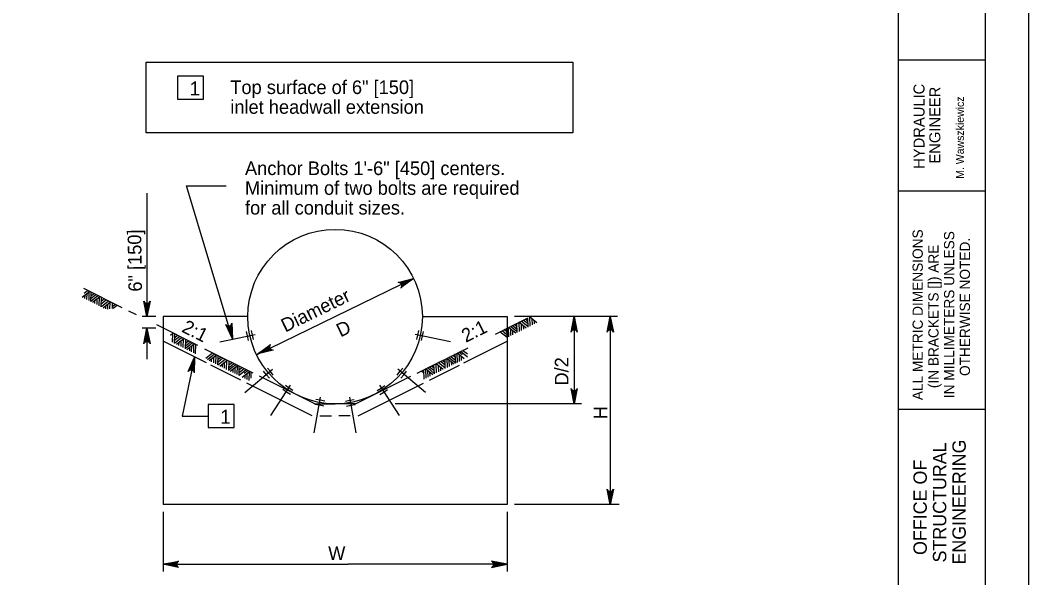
# Model space of a CAD drawing. Extents: x 1083.1 to 1117.1, y 675.4 to 741.4.
# Drawn here: x 1105.58 to 1117.13, y 728.43 to 734.81 of the extents above; entities that cross this region are included whole.
import ezdxf

# ---------------------------------------------------------------- set-up
doc = ezdxf.new("R2010")
doc.units = 0
doc.layers.add('Level 1', color=7, linetype='Continuous')

msp = doc.modelspace()

# ---------------------------------------------------------------- linework, layer by layer
at = {"layer": 'Level 1'}
for p, q in [((1115.636, 719.854), (1115.636, 740.854)), ((1116.626, 734.354), (1115.636, 734.354)), ((1107.384, 734.171), (1107.384, 733.909)), ((1107.683, 734.171), (1107.384, 734.171)), ((1107.683, 733.909), (1107.683, 734.171)), ((1107.384, 733.909), (1107.683, 733.909)), ((1108.013, 731.162), (1107.486, 732.915)), ((1107.486, 732.915), (1107.941, 732.915)), ((1107.034, 732.833), (1107.034, 731.418)), ((1116.626, 732.854), (1115.636, 732.854)), ((1110.085, 731.855), (1108.29, 730.98)), ((1109.928, 731.806), (1110.085, 731.855)), ((1109.938, 731.8), (1110.085, 731.855)), ((1109.947, 731.788), (1110.085, 731.855)), ((1109.95, 731.777), (1110.085, 731.855)), ((1109.95, 731.765), (1110.085, 731.855)), ((1106.751, 731.519), (1106.31, 731.74)), ((1106.293, 731.64), (1106.376, 731.707)), ((1106.316, 731.687), (1106.355, 731.718)), ((1106.324, 731.625), (1106.326, 731.667)), ((1106.347, 731.613), (1106.35, 731.685)), ((1106.371, 731.601), (1106.374, 731.705)), ((1106.392, 731.591), (1106.396, 731.697)), ((1106.392, 731.594), (1106.473, 731.658)), ((1106.393, 731.625), (1106.45, 731.67)), ((1106.394, 731.657), (1106.426, 731.682)), ((1106.411, 731.582), (1106.495, 731.648)), ((1106.463, 731.555), (1106.465, 731.625)), ((1106.487, 731.543), (1106.49, 731.644)), ((1106.511, 731.531), (1106.515, 731.638)), ((1106.514, 731.598), (1106.544, 731.623)), ((1106.438, 731.568), (1106.439, 731.604)), ((1106.512, 731.534), (1106.592, 731.599)), ((1106.513, 731.567), (1106.567, 731.611)), ((1106.534, 731.52), (1106.618, 731.586)), ((1106.562, 731.506), (1106.563, 731.543)), ((1106.586, 731.503), (1106.588, 731.563)), ((1106.611, 731.507), (1106.614, 731.583)), ((1106.638, 731.511), (1106.64, 731.575)), ((1106.638, 731.504), (1106.639, 731.505)), ((1106.639, 731.534), (1106.67, 731.56)), ((1106.649, 731.513), (1106.694, 731.548)), ((1107.011, 731.578), (1107.034, 731.418)), ((1107.022, 731.572), (1107.034, 731.418)), ((1107.058, 731.58), (1107.034, 731.418)), ((1107.048, 731.574), (1107.034, 731.418)), ((1107.034, 731.571), (1107.034, 731.418)), ((1106.916, 731.437), (1106.828, 731.481)), ((1107.136, 731.418), (1106.979, 731.418)), ((1107.219, 731.418), (1107.219, 729.265)), ((1108.189, 731.418), (1107.219, 731.418)), ((1110.186, 731.418), (1111.156, 731.418)), ((1111.021, 731.218), (1111.389, 731.402)), ((1111.156, 731.418), (1111.156, 729.265)), ((1112.419, 731.418), (1111.239, 731.418)), ((1111.394, 731.365), (1111.363, 731.389)), ((1111.396, 731.298), (1111.393, 731.404)), ((1111.497, 731.348), (1111.413, 731.414)), ((1111.42, 731.31), (1111.417, 731.411)), ((1111.445, 731.322), (1111.443, 731.391)), ((1111.898, 731.255), (1111.923, 731.418)), ((1111.909, 731.262), (1111.923, 731.418)), ((1111.923, 731.418), (1111.923, 730.732)), ((1111.923, 731.264), (1111.923, 731.418)), ((1111.934, 731.263), (1111.923, 731.418)), ((1111.945, 731.257), (1111.923, 731.418)), ((1112.312, 731.255), (1112.336, 731.418)), ((1112.322, 731.262), (1112.336, 731.418)), ((1112.336, 731.418), (1112.336, 730.217)), ((1112.336, 731.264), (1112.336, 731.418)), ((1112.348, 731.263), (1112.336, 731.418)), ((1112.359, 731.257), (1112.336, 731.418)), ((1107.136, 731.285), (1106.979, 731.285)), ((1107.009, 731.123), (1107.034, 731.285)), ((1107.019, 731.129), (1107.034, 731.285)), ((1107.034, 731.285), (1107.034, 730.931)), ((1107.034, 731.132), (1107.034, 731.285)), ((1107.045, 731.131), (1107.034, 731.285)), ((1107.056, 731.125), (1107.034, 731.285)), ((1107.616, 731.087), (1107.146, 731.322)), ((1107.955, 731.313), (1108.013, 731.162)), ((1107.967, 731.31), (1108.013, 731.162)), ((1107.978, 731.311), (1108.013, 731.162)), ((1107.991, 731.317), (1108.013, 731.162)), ((1108, 731.326), (1108.013, 731.162)), ((1111.155, 731.177), (1111.152, 731.284)), ((1111.255, 731.227), (1111.171, 731.293)), ((1111.177, 731.188), (1111.173, 731.291)), ((1111.232, 731.273), (1111.193, 731.304)), ((1111.27, 731.27), (1111.214, 731.315)), ((1111.271, 731.242), (1111.232, 731.273)), ((1111.269, 731.301), (1111.238, 731.327)), ((1111.271, 731.235), (1111.268, 731.342)), ((1111.374, 731.286), (1111.29, 731.353)), ((1111.297, 731.248), (1111.294, 731.35)), ((1111.396, 731.301), (1111.315, 731.365)), ((1111.322, 731.26), (1111.32, 731.329)), ((1111.395, 731.334), (1111.34, 731.378)), ((1111.346, 731.273), (1111.345, 731.309)), ((1111.47, 731.334), (1111.469, 731.37)), ((1107.305, 731.207), (1107.332, 731.229)), ((1107.325, 731.124), (1107.329, 731.226)), ((1107.349, 731.112), (1107.353, 731.219)), ((1107.35, 731.115), (1107.431, 731.18)), ((1107.351, 731.148), (1107.406, 731.192)), ((1107.352, 731.179), (1107.382, 731.204)), ((1107.372, 731.101), (1107.456, 731.167)), ((1107.449, 731.063), (1107.452, 731.164)), ((1107.868, 731.128), (1108.272, 731.214)), ((1108.186, 731.196), (1108.175, 731.246)), ((1108.197, 731.146), (1108.186, 731.196)), ((1108.241, 731.207), (1108.23, 731.257)), ((1108.253, 731.157), (1108.241, 731.207)), ((1110.507, 731.128), (1110.103, 731.214)), ((1110.122, 731.157), (1110.133, 731.207)), ((1110.133, 731.207), (1110.145, 731.257)), ((1110.177, 731.146), (1110.189, 731.196)), ((1110.189, 731.196), (1110.2, 731.246)), ((1111.155, 731.18), (1111.074, 731.245)), ((1111.154, 731.211), (1111.098, 731.256)), ((1111.153, 731.243), (1111.122, 731.269)), ((1111.2, 731.2), (1111.198, 731.272)), ((1111.223, 731.211), (1111.222, 731.253)), ((1107.715, 730.887), (1107.219, 731.135)), ((1107.4, 731.087), (1107.401, 731.124)), ((1107.424, 731.075), (1107.426, 731.144)), ((1107.475, 731.05), (1107.478, 731.156)), ((1107.475, 731.056), (1107.514, 731.088)), ((1107.476, 731.085), (1107.532, 731.129)), ((1107.477, 731.115), (1107.508, 731.141)), ((1107.491, 731.041), (1107.574, 731.108)), ((1107.514, 731.088), (1107.553, 731.119)), ((1107.523, 731.026), (1107.524, 731.067)), ((1107.545, 731.014), (1107.548, 731.086)), ((1107.569, 731.002), (1107.572, 731.106)), ((1107.591, 730.992), (1107.594, 731.098)), ((1108.249, 730.771), (1107.697, 731.047)), ((1108.437, 731.08), (1108.303, 730.99)), ((1108.437, 731.068), (1108.303, 730.99)), ((1108.44, 731.057), (1108.303, 730.99)), ((1108.449, 731.045), (1108.303, 730.99)), ((1110.126, 730.771), (1110.709, 731.062)), ((1110.66, 730.887), (1111.156, 731.135)), ((1107.521, 730.801), (1107.579, 730.955)), ((1107.532, 730.805), (1107.579, 730.955)), ((1107.547, 730.805), (1107.579, 730.955)), ((1107.557, 730.801), (1107.579, 730.955)), ((1107.567, 730.793), (1107.579, 730.955)), ((1107.709, 730.942), (1107.785, 731.003)), ((1107.728, 730.927), (1107.808, 730.991)), ((1107.746, 730.914), (1107.83, 730.98)), ((1107.773, 730.901), (1107.774, 730.936)), ((1107.798, 730.888), (1107.8, 730.957)), ((1107.823, 730.876), (1107.825, 730.977)), ((1107.846, 730.864), (1107.85, 730.97)), ((1107.847, 730.867), (1107.928, 730.931)), ((1107.848, 730.9), (1107.903, 730.944)), ((1107.849, 730.931), (1107.88, 730.955)), ((1108.459, 731.038), (1108.303, 730.99)), ((1110.448, 730.823), (1110.445, 730.93)), ((1110.548, 730.874), (1110.465, 730.94)), ((1110.472, 730.836), (1110.469, 730.937)), ((1110.567, 730.886), (1110.486, 730.951)), ((1110.566, 730.917), (1110.509, 730.962)), ((1110.565, 730.949), (1110.533, 730.974)), ((1110.567, 730.883), (1110.563, 730.99)), ((1110.666, 730.933), (1110.583, 730.999)), ((1110.588, 730.894), (1110.585, 730.997)), ((1110.643, 730.979), (1110.604, 731.01)), ((1110.612, 730.905), (1110.609, 730.978)), ((1110.704, 730.955), (1110.623, 731.019)), ((1110.635, 730.917), (1110.633, 730.959)), ((1110.703, 730.986), (1110.646, 731.031)), ((1108.108, 730.69), (1107.765, 730.862)), ((1107.869, 730.852), (1107.953, 730.919)), ((1107.897, 730.839), (1107.898, 730.875)), ((1107.921, 730.826), (1107.923, 730.895)), ((1107.946, 730.814), (1107.949, 730.916)), ((1107.972, 730.801), (1107.975, 730.908)), ((1107.972, 730.808), (1108.011, 730.839)), ((1107.973, 730.836), (1108.029, 730.881)), ((1107.974, 730.867), (1108.005, 730.893)), ((1107.988, 730.793), (1108.072, 730.859)), ((1108.011, 730.839), (1108.05, 730.87)), ((1108.02, 730.777), (1108.021, 730.819)), ((1108.043, 730.766), (1108.045, 730.838)), ((1108.066, 730.754), (1108.069, 730.857)), ((1108.088, 730.743), (1108.091, 730.85)), ((1108.088, 730.746), (1108.168, 730.811)), ((1108.089, 730.777), (1108.145, 730.822)), ((1108.09, 730.809), (1108.121, 730.835)), ((1108.153, 730.549), (1108.469, 730.815)), ((1108.446, 730.788), (1108.413, 730.827)), ((1110.222, 730.549), (1109.906, 730.815)), ((1109.929, 730.788), (1109.962, 730.827)), ((1110.306, 730.753), (1110.223, 730.819)), ((1110.228, 730.714), (1110.225, 730.817)), ((1110.283, 730.799), (1110.244, 730.83)), ((1110.322, 730.796), (1110.265, 730.841)), ((1110.267, 730.69), (1110.61, 730.862)), ((1110.321, 730.827), (1110.289, 730.852)), ((1110.323, 730.761), (1110.319, 730.867)), ((1110.425, 730.812), (1110.342, 730.879)), ((1110.348, 730.774), (1110.345, 730.875)), ((1110.448, 730.827), (1110.367, 730.891)), ((1110.373, 730.786), (1110.371, 730.855)), ((1110.447, 730.86), (1110.392, 730.904)), ((1110.398, 730.798), (1110.396, 730.835)), ((1110.445, 730.89), (1110.415, 730.915)), ((1110.496, 730.848), (1110.494, 730.917)), ((1110.522, 730.86), (1110.52, 730.896)), ((1108.125, 730.724), (1108.208, 730.791)), ((1108.148, 730.771), (1108.187, 730.802)), ((1108.157, 730.709), (1108.158, 730.751)), ((1108.179, 730.697), (1108.182, 730.769)), ((1108.203, 730.685), (1108.206, 730.789)), ((1108.226, 730.714), (1108.228, 730.781)), ((1108.954, 730.418), (1108.322, 730.734)), ((1108.402, 730.753), (1108.369, 730.793)), ((1108.435, 730.714), (1108.402, 730.753)), ((1108.479, 730.749), (1108.446, 730.788)), ((1109.421, 730.418), (1110.053, 730.734)), ((1109.896, 730.749), (1109.929, 730.788)), ((1109.94, 730.714), (1109.973, 730.753)), ((1109.973, 730.753), (1110.006, 730.793)), ((1110.205, 730.769), (1110.173, 730.794)), ((1110.207, 730.703), (1110.203, 730.81)), ((1110.252, 730.726), (1110.249, 730.798)), ((1110.275, 730.737), (1110.273, 730.779)), ((1110.322, 730.767), (1110.283, 730.799)), ((1111.923, 730.732), (1111.923, 730.418)), ((1108.923, 730.283), (1108.177, 730.656)), ((1108.452, 730.285), (1108.677, 730.631)), ((1108.632, 730.554), (1108.589, 730.582)), ((1108.662, 730.6), (1108.619, 730.628)), ((1108.705, 730.572), (1108.662, 730.6)), ((1109.452, 730.283), (1110.198, 730.656)), ((1109.67, 730.572), (1109.713, 730.6)), ((1109.923, 730.285), (1109.698, 730.631)), ((1109.713, 730.6), (1109.756, 730.628)), ((1109.743, 730.554), (1109.786, 730.582)), ((1111.948, 730.58), (1111.923, 730.418)), ((1108.675, 730.526), (1108.632, 730.554)), ((1108.948, 730.088), (1109.02, 730.495)), ((1109.018, 730.46), (1108.968, 730.469)), ((1109.427, 730.088), (1109.355, 730.495)), ((1109.356, 730.46), (1109.407, 730.469)), ((1109.7, 730.526), (1109.743, 730.554)), ((1111.9, 730.578), (1111.923, 730.418)), ((1111.912, 730.573), (1111.923, 730.418)), ((1111.937, 730.574), (1111.923, 730.418)), ((1111.923, 730.571), (1111.923, 730.418)), ((1107.734, 730.41), (1107.734, 730.149)), ((1108.033, 730.41), (1107.734, 730.41)), ((1108.033, 730.149), (1108.033, 730.41)), ((1108.954, 730.418), (1109.187, 730.418)), ((1109.007, 730.402), (1108.957, 730.411)), ((1109.058, 730.393), (1109.007, 730.402)), ((1109.069, 730.451), (1109.018, 730.46)), ((1109.421, 730.418), (1109.187, 730.418)), ((1109.306, 730.451), (1109.356, 730.46)), ((1109.317, 730.393), (1109.368, 730.402)), ((1109.368, 730.402), (1109.418, 730.411)), ((1112.008, 730.418), (1109.875, 730.418)), ((1116.626, 730.354), (1115.636, 730.354)), ((1109.014, 730.283), (1109.146, 730.283)), ((1109.361, 730.283), (1109.228, 730.283)), ((1107.734, 730.149), (1108.033, 730.149)), ((1112.336, 730.217), (1112.336, 729.265)), ((1112.361, 729.427), (1112.336, 729.265)), ((1112.314, 729.425), (1112.336, 729.265)), ((1112.325, 729.42), (1112.336, 729.265)), ((1112.351, 729.421), (1112.336, 729.265)), ((1112.336, 729.418), (1112.336, 729.265)), ((1111.156, 729.265), (1107.219, 729.265)), ((1112.437, 729.265), (1111.239, 729.265)), ((1107.219, 729.182), (1107.219, 728.498)), ((1111.156, 729.182), (1111.156, 728.498)), ((1107.38, 728.604), (1107.219, 728.582)), ((1107.374, 728.593), (1107.219, 728.582)), ((1107.219, 728.582), (1109.337, 728.582)), ((1107.372, 728.582), (1107.219, 728.582)), ((1107.375, 728.567), (1107.219, 728.582)), ((1107.381, 728.557), (1107.219, 728.582)), ((1111.156, 728.582), (1109.337, 728.582)), ((1110.993, 728.557), (1111.156, 728.582)), ((1110.995, 728.604), (1111.156, 728.582)), ((1110.999, 728.567), (1111.156, 728.582)), ((1111.001, 728.593), (1111.156, 728.582)), ((1111.002, 728.582), (1111.156, 728.582))]:
    msp.add_line(p, q, dxfattribs=at)
for points in [[(1083.126, 719.354), (1117.126, 719.354), (1117.126, 741.354), (1083.126, 741.354)], [(1085.126, 740.854), (1116.626, 740.854), (1116.626, 719.854), (1085.126, 719.854)], [(1107.024, 734.333), (1111.907, 734.333), (1111.907, 733.524), (1107.024, 733.524)]]:
    msp.add_lwpolyline(points, close=True, dxfattribs=at)
for points in [[(1109.91, 731.809), (1110.085, 731.855), (1109.941, 731.746)], [(1107.069, 731.595), (1107.034, 731.418), (1106.998, 731.595)], [(1111.888, 731.241), (1111.923, 731.418), (1111.958, 731.241)], [(1112.301, 731.241), (1112.336, 731.418), (1112.372, 731.241)], [(1106.998, 731.108), (1107.034, 731.285), (1107.069, 731.108)], [(1108.007, 731.343), (1108.013, 731.162), (1107.938, 731.327)], [(1108.477, 731.035), (1108.303, 730.99), (1108.446, 731.099)], [(1107.579, 730.955), (1107.436, 730.279), (1107.734, 730.279)], [(1107.507, 730.789), (1107.579, 730.955), (1107.576, 730.774)], [(1111.958, 730.595), (1111.923, 730.418), (1111.888, 730.595)], [(1112.372, 729.442), (1112.336, 729.265), (1112.301, 729.442)], [(1107.396, 728.546), (1107.219, 728.582), (1107.396, 728.617)], [(1110.978, 728.546), (1111.156, 728.582), (1110.978, 728.617)]]:
    msp.add_lwpolyline(points, dxfattribs=at)
for centre, start, end in [((1109.913, 731.771), 318.0819, 93.908), ((1107.034, 731.609), 202.0878, 337.9139), ((1107.969, 731.349), 215.3586, 351.1847), ((1111.923, 731.226), 22.0878, 157.9139), ((1112.336, 731.226), 22.0878, 157.9139), ((1107.034, 731.094), 22.0878, 157.9139), ((1108.474, 731.073), 138.0818, 273.908), ((1107.539, 730.768), 9.8492, 145.6753), ((1111.923, 730.61), 202.0878, 337.9139), ((1112.336, 729.456), 202.0878, 337.9139), ((1107.411, 728.582), 112.0878, 247.9139), ((1110.964, 728.582), 292.0861, 67.9122)]:
    msp.add_arc(centre, 0.0382, start, end, dxfattribs=at)
msp.add_ellipse((1109.187, 731.418), major_axis=(0.999, 0), ratio=0.999895, dxfattribs=at)

# ---------------------------------------------------------------- texts
for s, height, p in [('1', 0.16, (1107.523, 733.951)), ('Top surface of 6" [150]', 0.156, (1107.988, 733.967)), ('inlet headwall extension  ', 0.156, (1107.988, 733.741)), ('Anchor Bolts 1\'-6" [450] centers.', 0.156, (1108.156, 733.039)), ('Minimum of two bolts are required', 0.156, (1108.156, 732.813)), ('for all conduit sizes.', 0.156, (1108.156, 732.587)), ('1', 0.16, (1107.873, 730.191)), ('W', 0.156, (1109.108, 728.631))]:
    msp.add_text(s, height=height, dxfattribs=at).set_placement(p)
for s, height, rotation, p in [('HYDRAULIC', 0.126, 90, (1115.933, 733.111)), ('ENGINEER', 0.126, 90, (1116.114, 733.171)), ('M. Wawszkiewicz', 0.09, 90, (1116.383, 732.996)), ('6" [150]', 0.156, 90.8499, (1106.978, 731.705)), ('ALL METRIC DIMENSIONS', 0.117, 90, (1115.913, 730.461)), ('IN MILLIMETERS UNLESS', 0.117, 90, (1116.273, 730.484)), ('(IN BRACKETS []) ARE', 0.117, 90, (1116.093, 730.599)), ('OTHERWISE NOTED.', 0.117, 90, (1116.453, 730.738)), ('Diameter', 0.156, 25.9977, (1108.617, 731.235)), ('2:1', 0.156, 333.4374, (1107.422, 731.249)), ('D', 0.156, 25.9977, (1109.25, 731.179)), ('2:1', 0.156, 26.5626, (1110.683, 731.117)), ('D/2', 0.156, 90, (1111.858, 730.628)), ('H', 0.156, 90, (1112.302, 730.242)), ('STRUCTURAL', 0.153, 90, (1116.182, 728.602)), ('ENGINEERING', 0.153, 90, (1116.405, 728.578)), ('OFFICE OF', 0.153, 90, (1115.959, 728.688))]:
    msp.add_text(s, height=height, rotation=rotation, dxfattribs=at).set_placement(p)

doc.saveas('drawing.dxf')
